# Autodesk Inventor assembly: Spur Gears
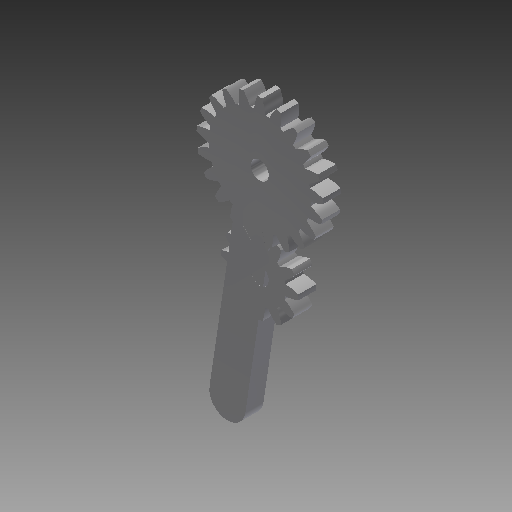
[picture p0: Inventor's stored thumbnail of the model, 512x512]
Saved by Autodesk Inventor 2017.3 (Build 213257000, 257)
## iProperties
Created: 2020-03
Part Number: Spur Gears
Document SubType Name: Assembly
Designer: Tim_G
Categories: <?xml version="1.0" encoding="UTF-16"?> <MemberInstance><Categories><FamilyTemplate/><ParamToTemplateMap><ParamToTemplate><ParamToTemplate CategoryParameter="//
ClientObjectVersion: 1
Author: Tim_G
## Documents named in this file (3)
- C:\Users\Tim_G\OneDrive - McMaster University\Documents\Documents\Books\McMaster First Year Courses\Winter Engineering 1C03\Project\Project Files (Prosthetic Frame Assembly)\Hand Assembly\Design Accelerator\Spur Gears3.iam
- C:\Users\Tim_G\OneDrive - McMaster University\Documents\Documents\Books\McMaster First Year Courses\Winter Engineering 1C03\Project\Project Files (Prosthetic Frame Assembly)\Hand Assembly\Design Accelerator\Spur Gear13.ipt
- C:\Users\Tim_G\OneDrive - McMaster University\Documents\Documents\Books\McMaster First Year Courses\Winter Engineering 1C03\Project\Project Files (Prosthetic Frame Assembly)\Hand Assembly\Design Accelerator\Spur Gear23.ipt
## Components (2 placed, 2 different names)
1. Spur Gear1:1 — Rotation:1
2. Spur Gear2:1 — Rotation:1
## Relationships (1: RelateRotation 1)
- Rotation:1 [RelateRotation]: Spur Gear1:1 ↔ Spur Gear2:1
